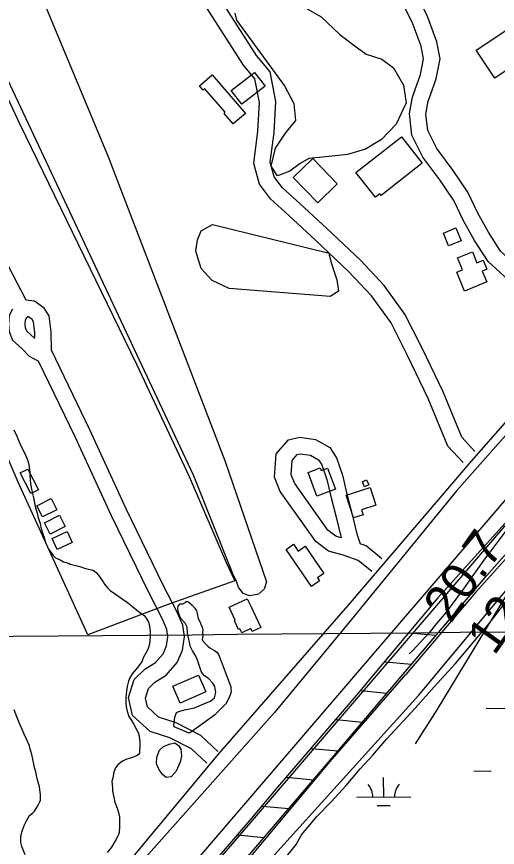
# Model space of a CAD drawing. Extents: x 3598634 to 3636690, y 517270 to 542944.
# Drawn here: x 3603298 to 3604186, y 528352 to 529886 of the extents above; entities that cross this region are included whole.
import ezdxf

# ---------------------------------------------------------------- set-up
doc = ezdxf.new("R2010")
doc.units = 0
for name, color, linetype in [('V-BLDG-OTLN', 7, 'Continuous'), ('V-FLOD-BASE', 7, 'Continuous'), ('V-GRID-MAJR', 7, 'Continuous'), ('V-LEVE-TOET', 7, 'Continuous'), ('V-RIVR-RANG', 7, 'Continuous'), ('V-ROAD-CNTR', 7, 'Continuous'), ('V-RRAP-FSHR', 7, 'Continuous'), ('V-SITE-OTLN', 7, 'Continuous'), ('V-SITE-VEGE', 7, 'Continuous'), ('V-SURV-LINE', 7, 'Continuous'), ('V-TOPO-MINR', 7, 'Continuous'), ('V-TOPO-SHOR', 7, 'Continuous'), ('V-WETL-SWMP', 7, 'Continuous')]:
    doc.layers.add(name, color=color, linetype=linetype)

msp = doc.modelspace()

# ---------------------------------------------------------------- linework, layer by layer
at = {"layer": 'V-BLDG-OTLN'}
for points in [[(3604147, 529824.2), (3604266.2, 529903.6), (3604299.9, 529852.9), (3604260.1, 529826.4), (3604265.9, 529817.7), (3604246, 529804.4), (3604240.8, 529812.2), (3604181.3, 529772.6)], [(3603720.9, 529707.3), (3603698.2, 529687.8), (3603681.4, 529707.3), (3603683.7, 529709.4), (3603646.2, 529752.8), (3603643.1, 529750.2), (3603636.1, 529758.3), (3603659.5, 529778.5)], [(3603694.9, 529749.4), (3603738, 529782.9), (3603757.5, 529757.8), (3603714.5, 529724.3)], [(3603925.1, 529598.1), (3604009.4, 529663.9), (3604047.4, 529615.2), (3603971.5, 529555.9), (3603969.2, 529558.9), (3603960.9, 529552.4)], [(3603854.4, 529542.2), (3603809, 529589.2), (3603845.2, 529624.2), (3603890.6, 529577.1)], [(3604096.2, 529462.7), (3604086.5, 529486.4), (3604109.4, 529495.8), (3604119.2, 529472.1)], [(3604166.6, 529396.3), (3604125.4, 529379.3), (3604111.2, 529414), (3604121.7, 529418.3), (3604112.6, 529440.5), (3604140, 529451.8), (3604148.3, 529431.7), (3604160.1, 529436.6), (3604167, 529419.8), (3604158.4, 529416.2)], [(3603324.8, 529005.4), (3603305.1, 529043.6), (3603319, 529050.8), (3603338.7, 529012.6)], [(3603872.4, 529052.3), (3603887, 529013.9), (3603853, 529000.9), (3603836.5, 529044.3), (3603859.1, 529052.9), (3603861, 529047.9)], [(3603941.1, 529017.8), (3603936.9, 529027.2), (3603944.8, 529030.8), (3603949, 529021.4)], [(3603907.1, 529002.6), (3603951.4, 529016.6), (3603961.7, 528984.1), (3603935.2, 528975.7), (3603938.3, 528966.1), (3603920.4, 528960.5)], [(3603335.7, 528983.2), (3603362.3, 528996.2), (3603372.5, 528975.4), (3603346, 528962.3)], [(3603349.7, 528951.5), (3603377.4, 528965.8), (3603388.2, 528944.8), (3603360.5, 528930.5)], [(3603364, 528922.7), (3603391.7, 528935.7), (3603401.3, 528915.5), (3603373.5, 528902.5)], [(3603842.8, 528834.1), (3603796.1, 528902.4), (3603810, 528911.9), (3603818.5, 528899.5), (3603831.5, 528908.4), (3603865.9, 528858.2), (3603853.8, 528850), (3603857.7, 528844.3)], [(3603749.6, 528758.1), (3603733.7, 528750.7), (3603731, 528756.5), (3603714.1, 528748.5), (3603710.6, 528756), (3603708.1, 528754.9), (3603700.5, 528770.9), (3603702.1, 528771.7), (3603690.8, 528795.7), (3603724.1, 528811.4), (3603730.7, 528797.4)], [(3603648, 528639.3), (3603600.5, 528618.8), (3603587.1, 528649.9), (3603634.6, 528670.4)]]:
    msp.add_lwpolyline(points, close=True, dxfattribs=at)
at = {"layer": 'V-FLOD-BASE'}
for points in [[(3604373.2, 529152.8), (3604289.3, 529054.6), (3604200.6, 528951.2), (3604076.2, 528813.1), (3603925.5, 528633), (3603780.1, 528463.8), (3603729.2, 528402.9)], [(3603729.2, 528402.9), (3603418.8, 528041.8), (3603301.7, 527898.6)]]:
    msp.add_lwpolyline(points, dxfattribs=at)
at = {"layer": 'V-GRID-MAJR'}
msp.add_spline([(3602797.9, 528737.7), (3608075.8, 528784.9), (3613353.8, 528832.9), (3618631.7, 528881.6), (3623909.7, 528931.1), (3629187.6, 528981.4), (3634465.5, 529032.5), (3634465.6, 529032.5)], degree=3, dxfattribs=at)
at = {"layer": 'V-LEVE-TOET'}
for points in [[(3605056.3, 530112.1), (3604790.8, 529796.4), (3604573.6, 529540.7), (3604353.6, 529284.8), (3604111.5, 529011.5), (3603916.4, 528772.2)], [(3605050.3, 529879.7), (3604869.8, 529677.4), (3604720.6, 529504.1), (3604655.2, 529427.9), (3604632.9, 529402.5), (3604606.9, 529368.5), (3604570.5, 529321.8), (3604548.7, 529296.4), (3604525.3, 529269.3), (3604483.9, 529222.5), (3604421.3, 529147.5), (3604419.3, 529139.5), (3604415.7, 529128.7), (3604411.5, 529117.3), (3604385.3, 529089), (3604295.3, 528989), (3604145.9, 528823), (3604017, 528671.5)], [(3603916.4, 528772.2), (3603774.8, 528601.3), (3603522, 528317.7)], [(3603565.9, 528137.9), (3603697, 528295), (3603877.6, 528510.8), (3604017, 528671.5)]]:
    msp.add_lwpolyline(points, dxfattribs=at)
at = {"layer": 'V-ROAD-CNTR'}
for points in [[(3604062.9, 529741.8), (3604073, 529771.3), (3604080.5, 529807.8), (3604074.7, 529839.7), (3604056.6, 529888), (3604031.5, 529937.6), (3603967.8, 530088.2), (3603916.3, 530202.5), (3603830.2, 530397.8), (3603685, 530691.3), (3603489.5, 531108), (3603336.6, 531418.2), (3603155.1, 531804.8), (3602975.8, 532172.2), (3602943.1, 532248.1)], [(3604034.5, 529751.5), (3604044, 529779.2), (3604049.9, 529808.2), (3604045.6, 529831.6), (3604029.1, 529875.9), (3604004.3, 529924.9), (3603940.3, 530076.2), (3603888.9, 530190.3), (3603803, 530385.1), (3603658, 530678.3), (3603462.5, 531095), (3603309.6, 531405.2), (3603128, 531791.8), (3602948.5, 532159.6), (3602915.5, 532236.3)], [(3604144.8, 529083.4), (3604120.4, 529109.6), (3604086.1, 529193.1), (3604047.1, 529274), (3604015.5, 529336.6), (3603976.9, 529389.6), (3603933.3, 529436.3), (3603871, 529494.9), (3603821.6, 529540.9), (3603789.5, 529569.8), (3603774.3, 529590), (3603766.8, 529617), (3603773.8, 529672.1), (3603777, 529729.2), (3603766.4, 529784.3), (3603741.3, 529814.4), (3603681.3, 529908.5), (3603636.3, 529978.9), (3603597.7, 530053.5), (3603565.2, 530118.1), (3603546.7, 530175.1)], [(3604122.9, 529063), (3604094.7, 529093.2), (3604058.7, 529180.8), (3604020.2, 529260.7), (3603989.8, 529321), (3603953.7, 529370.4), (3603912, 529415.1), (3603850.5, 529473), (3603801.3, 529518.7), (3603767.3, 529549.5), (3603747, 529576.5), (3603736.3, 529614.8), (3603743.9, 529674.8), (3603746.9, 529727.2), (3603738.4, 529771), (3603717.1, 529796.6), (3603656, 529892.3), (3603610.3, 529963.9), (3603571, 530039.9), (3603537.4, 530106.7), (3603518.2, 530165.8)], [(3605050.3, 530130.1), (3604771, 529801.9), (3604661.3, 529672.6), (3604570.1, 529565.2), (3604473.3, 529450.7), (3604385.1, 529346.4), (3604329.2, 529282.9), (3604137.8, 529065.5), (3604133.8, 529061), (3603910.1, 528798.8), (3603670.9, 528524.4), (3603437, 528243.4)], [(3603316.3, 529362.6), (3603282.8, 529426.7), (3603245.2, 529513.8), (3603234.7, 529543.9), (3603233, 529573.2), (3603229.6, 529612.3), (3603211.8, 529658), (3603180.6, 529706.5), (3603154, 529764.6), (3603148.5, 529772.9)], [(3604310.9, 529286.5), (3604271.7, 529334.5), (3604213.2, 529393.1), (3604168.9, 529433.8), (3604144.2, 529472.7), (3604123.4, 529509.2), (3604105.8, 529546.8), (3604080, 529584.5), (3604048.5, 529626.6), (3604028.2, 529666.9), (3604023.9, 529707), (3604029.5, 529737.4), (3604034.6, 529751.7)], [(3604334.1, 529305.4), (3604294, 529354.6), (3604233.9, 529414.8), (3604192.1, 529453.2), (3604169.9, 529488.2), (3604150, 529523), (3604131.9, 529561.7), (3604104.4, 529602), (3604074.1, 529642.5), (3604057.5, 529675.6), (3604054.2, 529705.9), (3604058.6, 529729.6), (3604062.9, 529741.6)], [(3603670.1, 528529.6), (3603638.9, 528558.9), (3603592.8, 528582.6), (3603560.7, 528592.7), (3603539.9, 528611.8), (3603536.3, 528627.7), (3603542, 528646), (3603553.9, 528657.6), (3603574.4, 528670.5), (3603594.7, 528693.6), (3603604.6, 528716.4), (3603608.2, 528741.3), (3603605.2, 528762.7), (3603594.9, 528786.4), (3603569.1, 528836.4), (3603500.9, 528977.1), (3603433.4, 529123.1), (3603362.8, 529270.2), (3603362.1, 529304.3), (3603358.8, 529333.4), (3603349.1, 529347.9), (3603331.6, 529360.6), (3603316.3, 529362.6)], [(3603291.1, 529346.1), (3603284.5, 529334.2), (3603283.5, 529317.6), (3603284.7, 529304.9), (3603290.9, 529288.8), (3603308, 529273.1), (3603321.8, 529259.4), (3603339.1, 529250.1)], [(3603332.3, 529293.4), (3603332.1, 529302.3), (3603329.8, 529322.8), (3603327.1, 529326.8), (3603320.2, 529331.8), (3603319.5, 529331.9), (3603316.4, 529329.9), (3603314, 529325.6), (3603313.6, 529318.1), (3603314.2, 529311.9), (3603316.4, 529306.1), (3603332.3, 529291.5)], [(3603649.6, 528507.7), (3603621.4, 528534.2), (3603581.4, 528554.7), (3603545.3, 528566.1), (3603512.7, 528596), (3603505.3, 528628.9), (3603515.6, 528662.2), (3603535.2, 528681.3), (3603554.7, 528693.6), (3603569.1, 528709.9), (3603575.5, 528724.6), (3603577.9, 528741.3), (3603576, 528754.5), (3603567.8, 528773.5), (3603542.3, 528823), (3603473.8, 528964.3), (3603406.3, 529110.3), (3603339.1, 529250.1)], [(3603954.3, 528861.8), (3603929, 528882.1), (3603901.6, 528891.6), (3603874.2, 528899.4), (3603851.2, 528917), (3603815.7, 528966.5), (3603785.4, 529009.6), (3603774.9, 529035.6), (3603778, 529078.8), (3603800.3, 529104.5), (3603820.8, 529109.5), (3603850.6, 529105.1), (3603876.9, 529090.6), (3603889.4, 529071.8), (3603899.9, 529039.6), (3603908.7, 529002.2), (3603916.8, 528972), (3603926.7, 528931), (3603932.7, 528912.6)], [(3603896.9, 528924.1), (3603887.9, 528926.7), (3603873, 528938.1), (3603840.2, 528983.9), (3603811.9, 529024.1), (3603805.3, 529040.3), (3603807.2, 529066.7), (3603816.7, 529077.6), (3603822.2, 529078.9), (3603840.9, 529076.2), (3603856, 529067.9), (3603862.2, 529058.6), (3603871, 529031.5), (3603879.6, 528994.9), (3603887.7, 528964.6), (3603897.6, 528923.9)], [(3603973, 528885.2), (3603943.7, 528908.8), (3603932.7, 528912.6)]]:
    msp.add_lwpolyline(points, dxfattribs=at)
at = {"layer": 'V-RRAP-FSHR'}
for p, q in [((3604072.7, 528743.4), (3604024.1, 528747.9)), ((3604027.4, 528690), (3603978.8, 528694.5)), ((3603982.2, 528636.6), (3603933.6, 528641.1)), ((3603936.9, 528583.2), (3603888.3, 528587.7)), ((3603891.7, 528529.8), (3603843.1, 528534.3)), ((3603846.3, 528476.5), (3603797.7, 528481.3)), ((3603800.8, 528423.3), (3603752.2, 528428.1)), ((3603755.2, 528370.2), (3603706.6, 528374.9))]:
    msp.add_line(p, q, dxfattribs=at)
for points in [[(3603091.9, 527329.5), (3603199.9, 527468.8), (3603247.5, 527548.8), (3603278.3, 527622.7), (3603286.7, 527683.9), (3603300.5, 527779.2), (3603315.4, 527834.6), (3603329.5, 527870), (3603360.8, 527909.2), (3603408.7, 527958.4), (3603635.1, 528229.7), (3603874.5, 528509.5), (3604166.6, 528854.3), (3604406.6, 529126.1), (3604875.1, 529685.7), (3605090, 529929.6)], [(3603091.9, 527329.5), (3603199.9, 527468.8), (3603247.5, 527548.8), (3603278.3, 527622.7), (3603286.7, 527683.9), (3603300.5, 527779.2), (3603315.4, 527834.6), (3603329.5, 527870), (3603360.8, 527909.2), (3603408.7, 527958.4), (3603635.1, 528229.7), (3603874.5, 528509.5), (3604095.1, 528769.9)]]:
    msp.add_lwpolyline(points, dxfattribs=at)
at = {"layer": 'V-SITE-OTLN'}
msp.add_lwpolyline([(3603701.4, 528844.5), (3603619.5, 528815.4), (3603574.4, 528799.7), (3603429.9, 528744.5), (3603301.5, 529026.3), (3603168.3, 529336.1), (3603095.5, 529485.2), (3603002.8, 529663.2), (3602914.7, 529849.1), (3603027.4, 529909.1), (3603168.6, 529977.6), (3603304, 529688.4), (3603519.7, 529244.7), (3603617.1, 529037), (3603685.4, 528878.3)], close=True, dxfattribs=at)
at = {"layer": 'V-SITE-VEGE'}
for p, q in [((3603218.5, 530224.7), (3603467.1, 529628.9)), ((3603624.9, 529039.3), (3603230.3, 529879.4)), ((3603467.1, 529628.9), (3603683.7, 529064.9)), ((3603293.3, 529123.1), (3603298.7, 529111.7)), ((3603298.7, 529111.7), (3603301.1, 529105.1)), ((3603301.1, 529105.1), (3603305.3, 529096.6)), ((3603305.3, 529096.6), (3603307.7, 529091.2)), ((3603307.7, 529091.2), (3603313.6, 529079.8)), ((3603313.6, 529079.8), (3603317.2, 529070.8)), ((3603317.2, 529070.8), (3603319, 529065.9)), ((3603319, 529065.9), (3603320.8, 529059.3)), ((3603683.7, 529064.9), (3603759.9, 528842.4)), ((3603320.8, 529059.3), (3603321.4, 529053.9)), ((3603321.4, 529053.9), (3603322.6, 529045.5)), ((3603322.6, 529045.5), (3603322.6, 529039.5)), ((3603322.6, 529039.5), (3603323.8, 529023.2)), ((3603697.5, 528857.3), (3603624.9, 529039.3)), ((3603323.8, 529023.2), (3603326.7, 529010.6)), ((3603326.7, 529010.6), (3603329.1, 529001)), ((3603329.1, 529001), (3603333.3, 528979.3)), ((3603333.3, 528979.3), (3603336.9, 528967.3)), ((3603336.9, 528967.3), (3603337.5, 528963.1)), ((3603337.5, 528963.1), (3603341.7, 528950.4)), ((3603341.7, 528950.4), (3603343.4, 528942.6)), ((3603343.4, 528942.6), (3603347, 528931.2)), ((3603347, 528931.2), (3603349.4, 528924.6)), ((3603349.4, 528924.6), (3603351.8, 528915.5)), ((3603351.8, 528915.5), (3603354.2, 528909.5)), ((3603354.2, 528909.5), (3603357.8, 528902.3)), ((3603357.8, 528902.3), (3603361.4, 528897.5)), ((3603361.4, 528897.5), (3603366.2, 528891.5)), ((3603366.2, 528891.5), (3603370.4, 528887.2)), ((3603370.4, 528887.2), (3603378.8, 528883)), ((3603378.8, 528883), (3603384.8, 528879.4)), ((3603384.8, 528879.4), (3603394.4, 528877)), ((3603394.4, 528877), (3603397.4, 528875.2)), ((3603397.4, 528875.2), (3603414.9, 528870.9)), ((3603414.9, 528870.9), (3603425.7, 528867.3)), ((3603425.7, 528867.3), (3603440.1, 528864.2)), ((3603440.1, 528864.2), (3603445.5, 528860)), ((3603445.5, 528860), (3603450.9, 528852.8)), ((3603450.9, 528852.8), (3603458.1, 528842.6)), ((3603704.2, 528843), (3603697.5, 528857.3)), ((3603458.1, 528842.6), (3603460.5, 528838.3)), ((3603460.5, 528838.3), (3603466.5, 528831.7)), ((3603707.9, 528832.9), (3603704.2, 528843)), ((3603759.9, 528842.4), (3603755.6, 528829.2)), ((3603466.5, 528831.7), (3603471.3, 528826.9)), ((3603471.3, 528826.9), (3603480.9, 528819.7)), ((3603480.9, 528819.7), (3603486.9, 528815.4)), ((3603717, 528821), (3603707.9, 528832.9)), ((3603729.1, 528816.5), (3603717, 528821)), ((3603745.1, 528820), (3603729.1, 528816.5)), ((3603755.6, 528829.2), (3603745.1, 528820)), ((3603486.9, 528815.4), (3603493.5, 528811.2)), ((3603493.5, 528811.2), (3603503.1, 528804.6)), ((3603503.1, 528804.6), (3603519.9, 528790.7)), ((3604171.3, 528765.8), (3604211.1, 528817.3)), ((3603519.9, 528790.7), (3603525.9, 528785.9)), ((3603525.9, 528785.9), (3603533.7, 528780.5)), ((3603533.7, 528780.5), (3603537.9, 528775.7)), ((3603537.9, 528775.7), (3603542.1, 528768.4)), ((3603542.1, 528768.4), (3603543.9, 528761.2)), ((3603543.9, 528761.2), (3603545.1, 528749.8)), ((3604108.8, 528692.1), (3604171.3, 528765.8)), ((3603545.1, 528749.8), (3603545.1, 528740.8)), ((3603543.9, 528727.5), (3603540.8, 528717.9)), ((3603545.1, 528740.8), (3603543.9, 528727.5)), ((3603537.8, 528711.9), (3603532.4, 528702.3)), ((3603540.8, 528717.9), (3603537.8, 528711.9)), ((3603530, 528696.3), (3603525.7, 528689.7)), ((3603532.4, 528702.3), (3603530, 528696.3)), ((3603521.5, 528684.3), (3603511.9, 528672.9)), ((3603525.7, 528689.7), (3603521.5, 528684.3)), ((3604069.3, 528648.5), (3604108.8, 528692.1)), ((3603507.7, 528665.1), (3603505.2, 528659.1)), ((3603511.9, 528672.9), (3603507.7, 528665.1)), ((3603505.2, 528659.1), (3603502.8, 528649.4)), ((3603501.6, 528641), (3603500.4, 528629)), ((3603502.8, 528649.4), (3603501.6, 528641)), ((3604034.5, 528609.7), (3604069.3, 528648.5)), ((3603500.4, 528629), (3603500.4, 528620)), ((3603500.4, 528620), (3603500.9, 528611.6)), ((3603300, 528590.3), (3603294.1, 528606.6)), ((3603500.9, 528611.6), (3603502.7, 528603.7)), ((3603502.7, 528603.7), (3603505.7, 528594.1)), ((3603982.3, 528552.5), (3604034.5, 528609.7)), ((3603304.2, 528580.1), (3603300, 528590.3)), ((3603505.7, 528594.1), (3603509.3, 528588.7)), ((3603509.3, 528588.7), (3603514.7, 528579.7)), ((3603309.6, 528568.6), (3603304.2, 528580.1)), ((3603514.7, 528579.7), (3603517.7, 528573)), ((3603517.7, 528573), (3603523.1, 528564.6)), ((3603312.6, 528561.4), (3603309.6, 528568.6)), ((3603316.8, 528552.4), (3603312.6, 528561.4)), ((3603523.1, 528564.6), (3603524.9, 528558)), ((3603524.9, 528558), (3603526.1, 528546.6)), ((3603322.2, 528539.7), (3603316.8, 528552.4)), ((3603526.1, 528546.6), (3603526, 528539.3)), ((3603956.2, 528522.4), (3603982.3, 528552.5)), ((3603322.8, 528536.1), (3603322.2, 528539.7)), ((3603326.4, 528524.1), (3603322.8, 528536.1)), ((3603526, 528539.3), (3603525.4, 528530.3)), ((3603525.4, 528530.3), (3603525.4, 528526.1)), ((3603328.2, 528515.1), (3603326.4, 528524.1)), ((3603331.7, 528500), (3603328.2, 528515.1)), ((3603494.1, 528511.7), (3603485.1, 528504.5)), ((3603500.1, 528514.7), (3603494.1, 528511.7)), ((3603509.8, 528517.7), (3603500.1, 528514.7)), ((3603513.4, 528518.9), (3603509.8, 528517.7)), ((3603520, 528521.3), (3603513.4, 528518.9)), ((3603523, 528523.1), (3603520, 528521.3)), ((3603525.4, 528526.1), (3603523, 528523.1)), ((3603933, 528497.2), (3603956.2, 528522.4)), ((3603334.1, 528491.6), (3603331.7, 528500)), ((3603480.9, 528499.1), (3603477.8, 528491.3)), ((3603485.1, 528504.5), (3603480.9, 528499.1)), ((3603906.9, 528466.5), (3603933, 528497.2)), ((3603336.5, 528479), (3603334.1, 528491.6)), ((3603476, 528481.1), (3603474.2, 528473.9)), ((3603477.8, 528491.3), (3603476, 528481.1)), ((3603338.3, 528473), (3603336.5, 528479)), ((3603340.7, 528463.9), (3603338.3, 528473)), ((3603474.2, 528473.9), (3603475.4, 528462.5)), ((3603879, 528436.3), (3603906.9, 528466.5)), ((3603341.3, 528458.5), (3603340.7, 528463.9)), ((3603342.5, 528450.1), (3603341.3, 528458.5)), ((3603475.4, 528462.5), (3603475.4, 528455.9)), ((3603475.4, 528455.9), (3603477.8, 528445)), ((3603338.8, 528431.5), (3603340.6, 528435.1)), ((3603340.6, 528435.1), (3603342.4, 528439.3)), ((3603342.4, 528439.3), (3603342.5, 528450.1)), ((3603477.8, 528445), (3603480.1, 528436)), ((3603480.1, 528436), (3603484.3, 528424.6)), ((3603852.9, 528409.2), (3603879, 528436.3)), ((3603331.6, 528419.5), (3603336.4, 528427.3)), ((3603336.4, 528427.3), (3603338.8, 528431.5)), ((3603484.3, 528424.6), (3603486.7, 528416.7)), ((3603315.9, 528400.2), (3603319.5, 528406.9)), ((3603319.5, 528406.9), (3603322.5, 528411.1)), ((3603322.5, 528411.1), (3603328, 528415.3)), ((3603328, 528415.3), (3603331.6, 528419.5)), ((3603486.7, 528416.7), (3603488.5, 528408.9)), ((3603488.5, 528408.9), (3603488.5, 528390.3)), ((3603824.5, 528375.4), (3603852.9, 528409.2)), ((3603308, 528380.4), (3603312.3, 528393)), ((3603312.3, 528393), (3603315.9, 528400.2)), ((3603488.5, 528390.3), (3603487.8, 528380.1)), ((3603306.2, 528372.6), (3603308, 528380.4)), ((3603486, 528374.1), (3603481.8, 528366.2)), ((3603487.8, 528380.1), (3603486, 528374.1)), ((3603814.9, 528357.8), (3603824.5, 528375.4)), ((3603306.2, 528361.2), (3603306.2, 528372.6)), ((3603308, 528354), (3603306.2, 528361.2)), ((3603481.8, 528366.2), (3603473.4, 528353)), ((3603314, 528338.9), (3603308, 528354)), ((3603473.4, 528353), (3603465.5, 528342.8)), ((3603789.4, 528326.5), (3603814.9, 528357.8))]:
    msp.add_line(p, q, dxfattribs=at)
msp.add_lwpolyline([(3603829.1, 529904), (3603860.7, 529885.3), (3603895, 529852.9), (3603921.2, 529833.4), (3603943.7, 529816.8), (3603972.6, 529807.5), (3603994.5, 529791.4), (3604012.7, 529759.2), (3604017.8, 529726.6), (3603999.3, 529687.3), (3603972.1, 529659.1), (3603942.8, 529641.5), (3603909.2, 529631.6), (3603869.4, 529626.9), (3603837.9, 529624.2), (3603822.1, 529614.8), (3603802.8, 529600.5), (3603780.4, 529592.1), (3603768.6, 529610.2), (3603776.5, 529643.2), (3603794.8, 529670.6), (3603813.8, 529694.4), (3603811.1, 529724.7), (3603792.8, 529758.7), (3603705.3, 529879.5), (3603701.9, 529892.6)], dxfattribs=at)
msp.add_lwpolyline([(3603870.9, 529450.5), (3603875.1, 529450.7), (3603875.8, 529445.9), (3603881.2, 529425.8), (3603889.7, 529399.8), (3603892.7, 529379.1), (3603877.5, 529369.1), (3603691.1, 529383.9), (3603659.7, 529399.1), (3603639.4, 529421.1), (3603629.5, 529453), (3603632.5, 529474), (3603639.2, 529490.3), (3603660.3, 529502.2)], close=True, dxfattribs=at)
at = {"layer": 'V-SURV-LINE'}
for points in [[(3603326, 527973.1), (3604734.6, 529615.8)], [(3604757.4, 529596.2), (3603348.8, 527953.6)]]:
    msp.add_lwpolyline(points, dxfattribs=at)
at = {"layer": 'V-TOPO-MINR'}
for points in [[(3605455.6, 530362.7), (3604918.8, 529698.1), (3604908.1, 529684.9), (3604897.3, 529671.8), (3604886.3, 529658.7), (3604875.4, 529645.7), (3604732.8, 529478.9), (3604651, 529382), (3604570.1, 529284.5), (3604490.4, 529186), (3604411.5, 529086.8), (3604219.9, 528842.7), (3604215.4, 528836.8), (3604211.1, 528830.8), (3604207, 528824.7), (3604203, 528818.4), (3604074.2, 528606.6), (3604034.4, 528543.7)], [(3604251.8, 529003.4), (3604172.2, 528897.6), (3604162.6, 528884.7), (3604153.1, 528871.7), (3604143.8, 528858.6), (3604134.5, 528845.5), (3604125.2, 528832.3), (3604115.8, 528819.3), (3604106.2, 528806.4), (3604096.4, 528793.6), (3604088.3, 528783.1), (3604074, 528765.4), (3604059.4, 528748), (3604044.2, 528731.2), (3604028.6, 528714.7), (3604023.5, 528709.6)]]:
    msp.add_lwpolyline(points, dxfattribs=at)
at = {"layer": 'V-TOPO-SHOR'}
for points in [[(3603694, 528644.2), (3603694.5, 528639.4), (3603692.3, 528632.3), (3603685.6, 528618.2), (3603664.1, 528596.6), (3603619.6, 528564.5), (3603616.9, 528563.2), (3603589.3, 528574.7), (3603588.8, 528576.7), (3603590.7, 528592.5), (3603593.6, 528601.7), (3603597.9, 528603.4), (3603608.5, 528606.5), (3603627, 528610.2), (3603648.5, 528619.1), (3603656.3, 528622.5), (3603663.6, 528628.6), (3603666.1, 528638.2), (3603664.2, 528649.2), (3603660.4, 528656.2), (3603653.5, 528663.5), (3603644.6, 528670), (3603640.1, 528675.8), (3603636.7, 528684.8), (3603632.7, 528697.7), (3603628.9, 528706.7), (3603623.5, 528715.2), (3603619.7, 528722.6), (3603617.9, 528730.9), (3603613.9, 528747.8), (3603613.2, 528758.8), (3603609.4, 528766.6), (3603601.6, 528774.7), (3603599.1, 528780.6), (3603596.9, 528787.6), (3603595.9, 528793.9), (3603597, 528797.5), (3603600.4, 528801.9), (3603605.2, 528802.1), (3603610.2, 528804.6), (3603611.4, 528806.2), (3603614.9, 528806.3), (3603617.8, 528804), (3603622.6, 528799.4), (3603627.5, 528794), (3603630.5, 528789), (3603631.3, 528786.6), (3603632.3, 528781.1), (3603632.8, 528777.6), (3603634.5, 528773.7), (3603636.6, 528769.4), (3603638.7, 528764.3), (3603640.8, 528758.8), (3603642.6, 528753.4), (3603641.5, 528749), (3603642.1, 528743.1), (3603641.8, 528739.9), (3603641.1, 528736.3), (3603641.9, 528734.4), (3603646.5, 528728.6), (3603651.3, 528723.6), (3603655.4, 528720.9), (3603663.8, 528715.6), (3603667.9, 528712.6), (3603671.5, 528708.7), (3603678, 528691.5), (3603687, 528666.9), (3603693.4, 528650.9), (3603694.2, 528648.5), (3603694, 528644.2)], [(3603601.9, 528533.6), (3603602.9, 528521.1), (3603600.2, 528509.7), (3603593, 528493.4), (3603583.8, 528482.4), (3603574.9, 528481.5), (3603567.6, 528486.7), (3603561.3, 528496.6), (3603556.8, 528506.6), (3603557.1, 528519.1), (3603562.1, 528531.8), (3603569.6, 528538.6), (3603580.2, 528543), (3603590.3, 528545.1), (3603597.6, 528540.6), (3603601.9, 528533.6)]]:
    msp.add_lwpolyline(points, dxfattribs=at)
at = {"layer": 'V-WETL-SWMP'}
for p, q in [((3604165.3, 528609), (3604265.3, 528609.9)), ((3603976.4, 528445.4), (3603976.1, 528481.4)), ((3604143, 528493.3), (3604175, 528493.6)), ((3603926.4, 528444.9), (3604026.4, 528445.8)), ((3603964.5, 528429.8), (3603988.5, 528430))]:
    msp.add_line(p, q, dxfattribs=at)
msp.add_lwpolyline([(3603445.3, 527974.1), (3604040.8, 528632.6), (3604355.7, 529010.5), (3604453, 529142.2), (3604470.2, 529170.8), (3604510.3, 529228), (3604544.6, 529256.7), (3604573.3, 529268.1), (3604613.3, 529285.3), (3604750.8, 529468.5), (3605243.2, 530023.9)], dxfattribs=at)
for centre, start, end in [((3603921.1, 528445.3), 359.7615, 41.3052), ((3604031.6, 528446.3), 139.7615, 181.3052)]:
    msp.add_arc(centre, 35.2, start, end, dxfattribs=at)

# ---------------------------------------------------------------- texts
at = {"layer": 'V-RIVR-RANG'}
for s, p in [('20.7', (3604099.8, 528764)), ('12.6', (3604180.4, 528704.8))]:
    msp.add_text(s, height=67, rotation=54.6283, dxfattribs=at).set_placement(p)

doc.saveas('drawing.dxf')
